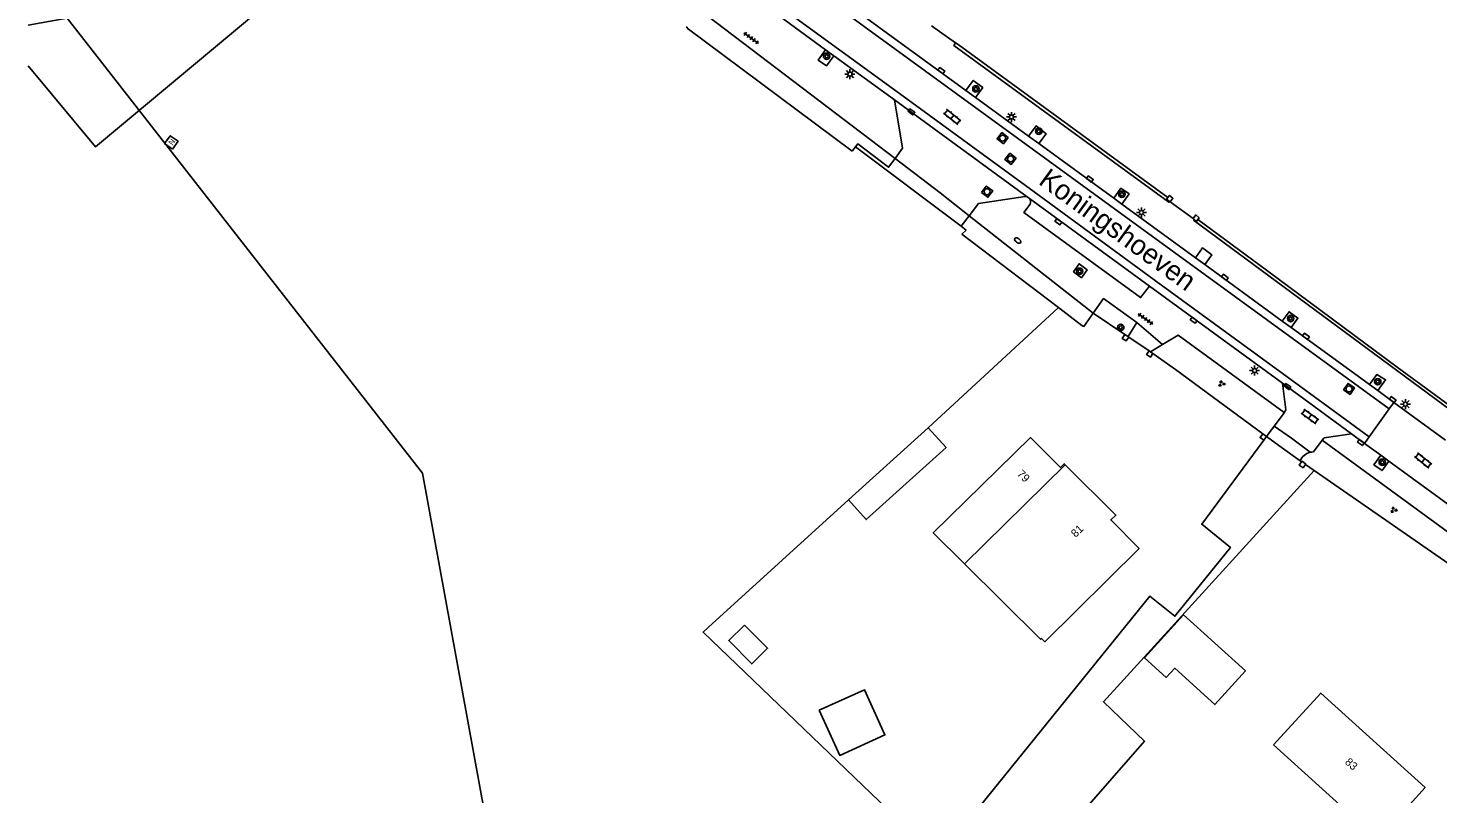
# Model space of a CAD drawing. Extents: x 135990 to 139000, y 393500 to 396000.
# Drawn here: x 136000 to 136176.2, y 395330 to 395425.7 of the extents above; entities that cross this region are included whole.
import ezdxf

# ---------------------------------------------------------------- set-up
doc = ezdxf.new("R2010")
doc.units = 0
for name, color, linetype in [('gg-afsc-erfafscheiding', 7, 'Continuous'), ('gg-afsc-hekwerk', 7, 'Continuous'), ('gg-afsc-muur', 7, 'Continuous'), ('gg-anno-huisnummerreeks BGT', 7, 'Continuous'), ('gg-anno-openbare ruimte label', 7, 'Continuous'), ('gg-bbg-bijgebouw', 7, 'Continuous'), ('gg-bbg-gedigitaliseerde bijgebouw', 7, 'Continuous'), ('gg-bbg-hoofdgebouw', 7, 'Continuous'), ('gg-bbg-tussenscheiding', 7, 'Continuous'), ('gg-knt-verharding', 7, 'Continuous'), ('gt-bbg-plantopografie pand', 7, 'Continuous'), ('gt-grn-groengrens', 7, 'Continuous'), ('gt-grn-vlakafsluiter', 7, 'Continuous'), ('gt-grn-weggrens', 7, 'Continuous'), ('gt-symb-boom', 7, 'Continuous'), ('gt-symb-brandkraan', 7, 'Continuous'), ('gt-symb-groenvak', 7, 'Continuous'), ('gt-symb-klinker verharding', 7, 'Continuous'), ('gt-symb-kolk', 7, 'Continuous'), ('gt-symb-lichtmast', 7, 'Continuous'), ('gt-symb-nortonput', 7, 'Continuous'), ('gt-symb-rioolschacht', 7, 'Continuous'), ('gt-symb-tegel verharding', 7, 'Continuous')]:
    doc.layers.add(name, color=color, linetype=linetype)

# ---------------------------------------------------------------- blocks, each defined once
blk = doc.blocks.new('gt0-KL1')
at = {"layer": 'gt-symb-klinker verharding'}
for p, q in [((-1.15, 0.3), (1.15, 0.3)), ((-1, -0.3), (-1, 0.3)), ((-0.5, 0.3), (-0.5, 0.45)), ((0, -0.3), (0, 0.3)), ((0.5, 0.3), (0.5, 0.45)), ((1, -0.3), (1, 0.3)), ((-1.15, -0.3), (1.15, -0.3)), ((-0.5, -0.45), (-0.5, -0.3)), ((0.5, -0.45), (0.5, -0.3))]:
    blk.add_line(p, q, dxfattribs=at)
blk = doc.blocks.new('gt0-BOOM')
at = {"layer": 'gt-symb-boom'}
for radius in [0.4, 0.2]:
    blk.add_circle((0, 0), radius, dxfattribs=at)
blk = doc.blocks.new('gt0-RS')
at = {"layer": 'gt-symb-rioolschacht'}
blk.add_lwpolyline([(-0.5, -0.5), (0.5, -0.5), (0.5, 0.5), (-0.5, 0.5)], close=True, dxfattribs=at)
blk.add_circle((0, 0), 0.375, dxfattribs=at)
blk = doc.blocks.new('gt0-LMAST')
at = {"layer": 'gt-symb-lichtmast'}
for p, q in [((-0.18, 0.17), (-0.45, 0.44)), ((-0.01, 0.25), (-0.01, 0.62)), ((0.17, 0.17), (0.44, 0.44)), ((-0.26, 0), (-0.63, 0)), ((-0.18, -0.18), (-0.45, -0.45)), ((-0.01, -0.25), (-0.01, -0.63)), ((0.44, -0.45), (0.17, -0.18)), ((0.24, 0), (0.62, 0))]:
    blk.add_line(p, q, dxfattribs=at)
blk.add_circle((-0.01, 0), 0.25, dxfattribs=at)
blk = doc.blocks.new('gt0-KOLK')
at = {"layer": 'gt-symb-kolk'}
blk.add_lwpolyline([(0, 0), (0.38, 0), (0.38, 0.4), (-0.38, 0.4), (-0.38, 0), (0, 0)], dxfattribs=at)
blk = doc.blocks.new('gt0-TEG1')
at = {"layer": 'gt-symb-tegel verharding'}
for p, q in [((-1.12, 0), (1.12, 0)), ((-0.9, -0.25), (-0.9, 0.25)), ((-0.45, -0.25), (-0.45, 0.25)), ((0, -0.25), (0, 0.25)), ((0.45, -0.25), (0.45, 0.25)), ((0.9, -0.25), (0.9, 0.25))]:
    blk.add_line(p, q, dxfattribs=at)
blk = doc.blocks.new('gt0-NPUT')
at = {"layer": 'gt-symb-nortonput'}
blk.add_lwpolyline([(-0.57, -0.61), (-0.57, 0.59), (0.63, 0.59), (0.63, -0.61)], close=True, dxfattribs=at)
blk.add_text('N', height=0.7, dxfattribs=at).set_placement((-0.22, -0.38))
blk = doc.blocks.new('gt0-GRVAK')
at = {"layer": 'gt-symb-groenvak'}
for p, q in [((-0.11, 0.19), (-0.23, 0.24)), ((-0.18, 0.15), (0.09, 0.15)), ((-0.09, 0.21), (-0.16, 0.32)), ((-0.05, 0.21), (-0.05, 0.39)), ((0, 0.21), (0.06, 0.32)), ((0.01, 0.19), (0.13, 0.24)), ((0.26, -0.05), (0.2, 0.06)), ((0.3, -0.05), (0.3, 0.13)), ((0.35, -0.05), (0.41, 0.06)), ((-0.25, -0.23), (-0.36, -0.18)), ((-0.32, -0.26), (-0.05, -0.26)), ((-0.23, -0.21), (-0.29, -0.09)), ((-0.18, -0.2), (-0.18, -0.02)), ((-0.14, -0.21), (-0.07, -0.09)), ((-0.12, -0.23), (0, -0.18)), ((0.24, -0.07), (0.12, -0.02)), ((0.17, -0.11), (0.44, -0.11)), ((0.37, -0.07), (0.49, -0.02))]:
    blk.add_line(p, q, dxfattribs=at)
blk = doc.blocks.new('gt0-BR')
at = {"layer": 'gt-symb-brandkraan'}
for centre, radius, start, end in [((-0.24, 0), 0.206, 107.5669, 252.4331), ((0.6, -2.66), 3, 106.892, 107.5669), ((0, -0.69), 0.938, 73.108, 106.892), ((-0.6, -2.66), 3, 72.4331, 73.108), ((0.24, 0), 0.206, 287.567, 72.4331), ((0.6, 2.66), 3, 252.4331, 253.108), ((0, 0.69), 0.938, 253.108, 286.8921), ((-0.6, 2.66), 3, 286.8921, 287.567)]:
    blk.add_arc(centre, radius, start, end, dxfattribs=at)

msp = doc.modelspace()

# ---------------------------------------------------------------- linework, layer by layer
at = {"layer": 'gg-afsc-erfafscheiding'}
for p, q in [((136142.43, 395404.557), (136116.208, 395423.664)), ((136154.736, 395395.468), (136146.18, 395401.831)), ((136128.751, 395390.797), (136112.485, 395375.777)), ((136143.357, 395383.056), (136140.562, 395385.074)), ((136154.284, 395375.032), (136143.357, 395383.056)), ((136171.075, 395383.358), (136191.19, 395368.557)), ((136156.758, 395373.232), (136154.741, 395374.699)), ((136158.955, 395371.634), (136156.758, 395373.232)), ((136159.131, 395371.512), (136158.955, 395371.634)), ((136160.697, 395370.426), (136159.608, 395371.181)), ((136181.375, 395356.08), (136160.697, 395370.426))]:
    msp.add_line(p, q, dxfattribs=at)
msp.add_lwpolyline([(136102.508, 395366.777), (136085.019, 395350.862), (136084.347, 395350.25), (136113.72, 395322.039), (136140.176, 395354.76), (136143.299, 395352.235), (136150.245, 395360.826), (136146.652, 395363.731), (136154.412, 395374.221)], dxfattribs=at)
at = {"layer": 'gg-afsc-hekwerk'}
for p, q in [((136103.402, 395410.902), (136116.597, 395400.96)), ((136103.402, 395410.902), (136116.597, 395400.96)), ((136116.597, 395400.96), (136117.234, 395400.48)), ((136116.597, 395400.96), (136117.234, 395400.48)), ((136117.234, 395400.48), (136116.671, 395399.97)), ((136117.234, 395400.48), (136116.671, 395399.97)), ((136154.736, 395395.468), (136171.075, 395383.358)), ((136154.736, 395395.468), (136171.075, 395383.358))]:
    msp.add_line(p, q, dxfattribs=at)
at = {"layer": 'gg-afsc-muur'}
for p, q in [((136142.716, 395404.015), (136142.662, 395404.061)), ((136145.563, 395401.939), (136145.692, 395401.83)), ((136137.044, 395387.441), (136137.443, 395387.174)), ((136137.443, 395387.174), (136137.526, 395387.118)), ((136140.087, 395385.408), (136140.262, 395385.291)), ((136140.262, 395385.291), (136140.562, 395385.074)), ((136154.284, 395375.032), (136154.741, 395374.699)), ((136154.741, 395374.699), (136154.412, 395374.221))]:
    msp.add_line(p, q, dxfattribs=at)
for points in [[(136142.662, 395404.061), (136142.29, 395404.373), (136142.43, 395404.557)], [(136142.43, 395404.557), (136142.63, 395404.819), (136143.056, 395404.46), (136142.716, 395404.015)], [(136145.563, 395401.939), (136145.903, 395402.385), (136146.329, 395402.026), (136146.18, 395401.831)], [(136146.18, 395401.831), (136145.989, 395401.581), (136145.692, 395401.83)], [(136137.526, 395387.118), (136137.204, 395386.636), (136136.722, 395386.958), (136137.044, 395387.441)], [(136140.562, 395385.074), (136140.247, 395384.603), (136139.765, 395384.925), (136140.087, 395385.408)], [(136154.412, 395374.221), (136153.943, 395374.562), (136154.284, 395375.032)], [(136159.608, 395371.181), (136159.315, 395370.779), (136158.846, 395371.12), (136159.131, 395371.512)], [(136159.608, 395371.181), (136159.659, 395371.252), (136159.19, 395371.593), (136159.131, 395371.512)]]:
    msp.add_lwpolyline(points, dxfattribs=at)
at = {"layer": 'gg-bbg-bijgebouw'}
msp.add_lwpolyline([(136142.221, 395344.59), (136143.271, 395345.74), (136148.291, 395341.19), (136152.121, 395345.4), (136144.371, 395352.42), (136139.501, 395347.05), (136142.221, 395344.59)], dxfattribs=at)
at = {"layer": 'gg-bbg-gedigitaliseerde bijgebouw'}
msp.add_line((136102.508, 395366.777), (136112.485, 395375.777), dxfattribs=at)
for points in [[(136112.485, 395375.777), (136114.704, 395373.317), (136104.726, 395364.317), (136102.508, 395366.777)], [(136089.51, 395351.128), (136092.403, 395348.232), (136090.416, 395346.275), (136087.544, 395349.191), (136089.51, 395351.128)], [(136098.86, 395340.499), (136104.512, 395343.047), (136107.06, 395337.395), (136101.408, 395334.847), (136098.86, 395340.499)]]:
    msp.add_lwpolyline(points, dxfattribs=at)
at = {"layer": 'gg-bbg-hoofdgebouw'}
for points in [[(136129.58, 395371.172), (136129.471, 395371.28), (136129.011, 395370.8), (136125.241, 395374.56), (136113.111, 395362.66), (136117.022, 395358.782)], [(136117.022, 395358.782), (136126.521, 395349.36), (136126.621, 395349.46), (136127.031, 395349.05), (136138.831, 395360.71), (136135.281, 395364.26), (136135.921, 395364.88), (136129.58, 395371.172)], [(136155.641, 395336.16), (136161.521, 395342.62), (136174.571, 395330.83), (136168.711, 395324.35), (136155.641, 395336.16)]]:
    msp.add_lwpolyline(points, dxfattribs=at)
at = {"layer": 'gg-bbg-tussenscheiding'}
msp.add_line((136129.58, 395371.172), (136117.022, 395358.782), dxfattribs=at)
at = {"layer": 'gg-knt-verharding'}
for p, q in [((136100.107, 395430.382), (136117.189, 395417.931)), ((136099.654, 395423.028), (136091.335, 395429.089)), ((136115.883, 395423.901), (136112.898, 395426)), ((136100.68, 395422.281), (136099.654, 395423.028)), ((136108.276, 395416.746), (136100.68, 395422.281)), ((136117.189, 395417.931), (136118.39, 395417.056)), ((136108.276, 395416.746), (136124.846, 395404.646)), ((136118.39, 395417.056), (136125.019, 395412.225)), ((136125.019, 395412.225), (136126.297, 395411.293)), ((136103.402, 395410.902), (136102.984, 395410.343)), ((136126.297, 395411.293), (136135.651, 395404.475)), ((136124.846, 395404.646), (136125.113, 395404.451)), ((136140.12, 395393.465), (136125.113, 395404.451)), ((136135.651, 395404.475), (136136.665, 395403.736)), ((136136.665, 395403.736), (136145.856, 395397.037)), ((136142.716, 395404.015), (136145.563, 395401.939)), ((136116.597, 395400.96), (136117.6, 395402.289)), ((136145.856, 395397.037), (136147.02, 395396.189)), ((136147.02, 395396.189), (136156.717, 395389.122)), ((136140.12, 395393.465), (136156.74, 395381.34)), ((136156.717, 395389.122), (136157.818, 395388.319)), ((136137.443, 395387.174), (136138.525, 395388.918)), ((136157.818, 395388.319), (136167.616, 395381.178)), ((136140.087, 395385.408), (136137.526, 395387.118)), ((136141.742, 395386.172), (136140.262, 395385.291)), ((136157.331, 395382.147), (136167.585, 395374.639)), ((136156.74, 395381.34), (136165.383, 395375.012)), ((136167.616, 395381.178), (136168.643, 395380.43)), ((136168.643, 395380.43), (136170.662, 395378.958)), ((136170.082, 395378.144), (136170.662, 395378.958)), ((136170.662, 395378.958), (136177.133, 395374.235)), ((136167.585, 395374.639), (136170.082, 395378.144)), ((136155.714, 395375.986), (136154.741, 395374.699)), ((136165.383, 395375.012), (136167.007, 395373.828)), ((136183.219, 395358.511), (136161.71, 395374.226)), ((136167.007, 395373.828), (136167.585, 395374.639)), ((136167.007, 395373.828), (136169.04, 395372.345)), ((136169.04, 395372.345), (136170.051, 395371.607)), ((136170.051, 395371.607), (136179.22, 395364.918))]:
    msp.add_line(p, q, dxfattribs=at)
for points in [[(136054.121, 395462.196), (136055.212, 395461.602), (136056.872, 395460.603), (136069.52, 395451.437), (136170.082, 395378.144)], [(136051.338, 395459.78), (136053.29, 395458.065), (136079.768, 395438.741), (136108.866, 395417.554), (136125.704, 395405.258)], [(136082.341, 395425.71), (136082.391, 395425.776), (136082.244, 395425.885)], [(136099.654, 395423.028), (136098.736, 395421.734), (136099.76, 395420.999), (136100.68, 395422.281)], [(136142.662, 395404.061), (136142.562, 395403.965), (136115.68, 395423.554), (136115.883, 395423.901)], [(136117.189, 395417.931), (136118.101, 395419.183), (136119.296, 395418.3), (136118.39, 395417.056)], [(136108.324, 395409.432), (136109.265, 395410.712), (136108.276, 395416.746)], [(136125.019, 395412.225), (136125.954, 395413.508), (136127.203, 395412.536), (136126.297, 395411.293)], [(136103.402, 395410.902), (136103.66, 395411.247), (136107.527, 395408.348), (136108.324, 395409.432)], [(136157.331, 395382.147), (136140.711, 395394.272), (136125.704, 395405.258)], [(136135.651, 395404.475), (136136.562, 395405.725), (136137.584, 395404.997), (136136.665, 395403.736)], [(136117.6, 395402.289), (136118.757, 395403.821), (136124.606, 395404.691), (136124.846, 395404.646)], [(136140.12, 395393.465), (136139.003, 395392.053), (136124.428, 395402.703), (136125.195, 395403.743)], [(136191.19, 395368.557), (136190.954, 395368.235), (136145.634, 395401.737), (136145.692, 395401.83)], [(136145.856, 395397.037), (136146.756, 395398.272), (136147.914, 395397.415), (136147.02, 395396.189)], [(136130.632, 395395.287), (136131.329, 395396.281), (136132.324, 395395.534), (136131.627, 395394.54), (136130.632, 395395.287)], [(136138.525, 395388.918), (136134.392, 395391.928), (136133.097, 395390.104)], [(136133.097, 395390.104), (136131.922, 395388.449), (136131.671, 395388.58)], [(136156.717, 395389.122), (136157.56, 395390.278), (136158.676, 395389.497), (136157.818, 395388.319)], [(136156.964, 395377.691), (136143.725, 395387.352), (136141.742, 395386.172)], [(136168.643, 395380.43), (136169.624, 395381.776), (136168.535, 395382.44), (136167.616, 395381.178)], [(136156.74, 395381.34), (136157.181, 395378.035), (136156.964, 395377.691)], [(136156.964, 395377.691), (136156.99, 395377.672), (136155.714, 395375.986)], [(136161.71, 395374.226), (136161.97, 395374.518), (136165.383, 395375.012)], [(136161.71, 395374.226), (136160.616, 395372.763), (136160.412, 395372.752), (136160.211, 395372.718)], [(136170.051, 395371.607), (136169.191, 395370.429), (136168.173, 395371.157), (136169.04, 395372.345)]]:
    msp.add_lwpolyline(points, dxfattribs=at)
for centre, radius, start, end in [((136124.603, 395404.033), 0.659, 333.86403, 39.349), ((136160.61, 395370.986), 1.778, 102.97633, 158.61582)]:
    msp.add_arc(centre, radius, start, end, dxfattribs=at)
at = {"layer": 'gt-bbg-plantopografie pand'}
msp.add_lwpolyline([(136000, 395426.076), (136004.873, 395426.966), (136049.276, 395370.103), (136073.967, 395234.994), (136000, 395221.477)], dxfattribs=at)
at = {"layer": 'gt-grn-groengrens'}
msp.add_line((136137.044, 395387.441), (136133.097, 395390.104), dxfattribs=at)
at = {"layer": 'gt-grn-vlakafsluiter'}
for p, q in [((136102.984, 395410.343), (136082.341, 395425.71)), ((136115.883, 395423.901), (136116.208, 395423.664)), ((136116.671, 395399.97), (136128.751, 395390.797)), ((136128.751, 395390.797), (136131.671, 395388.58))]:
    msp.add_line(p, q, dxfattribs=at)
for points in [[(136000, 395421.033), (136008.429, 395410.872), (136050.635, 395446.134)], [(136196.555, 395345.334), (136153.746, 395293.901), (136136.965, 395308.571), (136138.775, 395310.131), (136126.192, 395321.407), (136139.516, 395336.608), (136134.358, 395341.535), (136160.697, 395370.426)]]:
    msp.add_lwpolyline(points, dxfattribs=at)
at = {"layer": 'gt-grn-weggrens'}
for p, q in [((136108.324, 395409.432), (136083.883, 395427.998)), ((136133.097, 395390.104), (136117.6, 395402.289)), ((136141.742, 395386.172), (136138.525, 395388.918))]:
    msp.add_line(p, q, dxfattribs=at)
for points in [[(136117.6, 395402.289), (136113.969, 395405.144), (136108.324, 395409.432)], [(136160.211, 395372.718), (136157.85, 395374.474), (136155.714, 395375.986)]]:
    msp.add_lwpolyline(points, dxfattribs=at)

# ---------------------------------------------------------------- block references
at = {"layer": 'gt-symb-boom'}
for p in [(136099.775, 395422.214), (136118.433, 395418.131), (136126.284, 395412.843), (136136.674, 395404.964), (136131.403, 395395.345), (136157.765, 395389.437), (136136.53, 395388.32), (136168.65, 395381.539), (136169.211, 395371.476)]:
    msp.add_blockref('gt0-BOOM', p, dxfattribs=at)
at = {"layer": 'gt-symb-brandkraan', "rotation": -37.23665897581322}
msp.add_blockref('gt0-BR', (136123.666, 395399.178), dxfattribs=at)
at = {"layer": 'gt-symb-groenvak'}
for p in [(136149.122, 395381.283), (136170.631, 395365.516)]:
    msp.add_blockref('gt0-GRVAK', p, dxfattribs=at)
at = {"layer": 'gt-symb-klinker verharding'}
for p, rotation in [((136115.48, 395414.626), 141.41174435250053), ((136160.175, 395377.191), 144.0358437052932), ((136174.332, 395371.698), -38.25701687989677)]:
    msp.add_blockref('gt0-KL1', p, dxfattribs=dict(at, rotation=rotation))
at = {"layer": 'gt-symb-kolk'}
for p, rotation in [((136113.987, 395420.248), -36.09056723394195), ((136110.262, 395415.111), -36.629401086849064), ((136132.548, 395406.72), -36.09056723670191), ((136128.85, 395401.69), 143.8631550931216), ((136149.427, 395394.419), -36.090567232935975), ((136145.763, 395389.385), 143.5427899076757), ((136159.561, 395387.041), -36.09056723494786), ((136157.251, 395380.785), -36.50328298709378), ((136170.405, 395379.145), -36.09056723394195), ((136166.653, 395374.107), 144.52896067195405)]:
    msp.add_blockref('gt0-KOLK', p, dxfattribs=dict(at, rotation=rotation))
at = {"layer": 'gt-symb-lichtmast'}
for p in [(136102.703, 395419.977), (136122.889, 395414.622), (136139.126, 395402.686), (136153.266, 395382.929), (136172.12, 395378.732)]:
    msp.add_blockref('gt0-LMAST', p, dxfattribs=at)
at = {"layer": 'gt-symb-nortonput', "rotation": 54.56219853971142}
msp.add_blockref('gt0-NPUT', (136017.86, 395411.424), dxfattribs=at)
at = {"layer": 'gt-symb-rioolschacht'}
for p, rotation in [((136121.774, 395411.976), 142.02949833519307), ((136122.768, 395409.388), 142.27073011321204), ((136119.833, 395405.287), -36.09056723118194), ((136165.068, 395380.637), -34.53212456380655)]:
    msp.add_blockref('gt0-RS', p, dxfattribs=dict(at, rotation=rotation))
at = {"layer": 'gt-symb-tegel verharding'}
for p, rotation in [((136090.349, 395424.477), -35.80410590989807), ((136139.64, 395389.38), -35.51769786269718)]:
    msp.add_blockref('gt0-TEG1', p, dxfattribs=dict(at, rotation=rotation))

# ---------------------------------------------------------------- texts
at = {"layer": 'gg-anno-huisnummerreeks BGT'}
for s, rotation, p in [('79', 315.1, (136123.51, 395369.93)), ('81', 44.2, (136130.893, 395362.017)), ('83', 317.9, (136164.467, 395333.895))]:
    msp.add_text(s, height=1, rotation=rotation, dxfattribs=at).set_placement(p)
at = {"layer": 'gg-anno-openbare ruimte label'}
msp.add_text('Koningshoeven', height=2.5, rotation=323.9, dxfattribs=at).set_placement((136126.119, 395406.333))

doc.saveas('drawing.dxf')
